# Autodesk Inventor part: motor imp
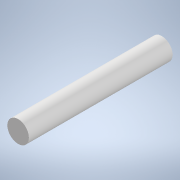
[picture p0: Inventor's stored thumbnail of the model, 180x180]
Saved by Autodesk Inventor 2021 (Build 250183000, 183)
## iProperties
Created: 2021-07
Part Number: motor imp
Material: Generic
Document SubType Name: Sheet Metal
Designer: user
Density: 1 g/cm^3
Sheet Metal Rule: Default_mm
Appearance: Default
Author: user
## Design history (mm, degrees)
sketch "Sketch1"
  geometry: 1 further point
sketch "Sketch2"
  geometry: C1 r 0.15 at (0, 0); 1 further point
  constraints: 1 centre point, 1 coincident
  dimensions: "d0" = 0.3 diameter of C1
extrude "Extrusion1" new body sketch "Sketch2" distance "d1" = 3.3; taper "d2" = 0 deg
body "Solid1"
other parameters: "Thickness" = 0.5, "BendRadius" = 0.5 (= Thickness), "BendReliefWidth" = 0.5 (= Thickness), "BendReliefDepth" = 0.25 (= 0.5 x Thickness), "CornerReliefSize" = 2 (= 4 x Thickness), "SeamGap" = 0.01, "MinimumRemnant" = 1 (= 2 x Thickness), "TransitionRadius" = 0.5 (= BendRadius), "JacobiRadiusSize" = 0.5 (= BendRadius), "GapSize" = 0.5 (= Thickness)
